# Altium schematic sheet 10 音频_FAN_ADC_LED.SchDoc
size 420 x 297 mm
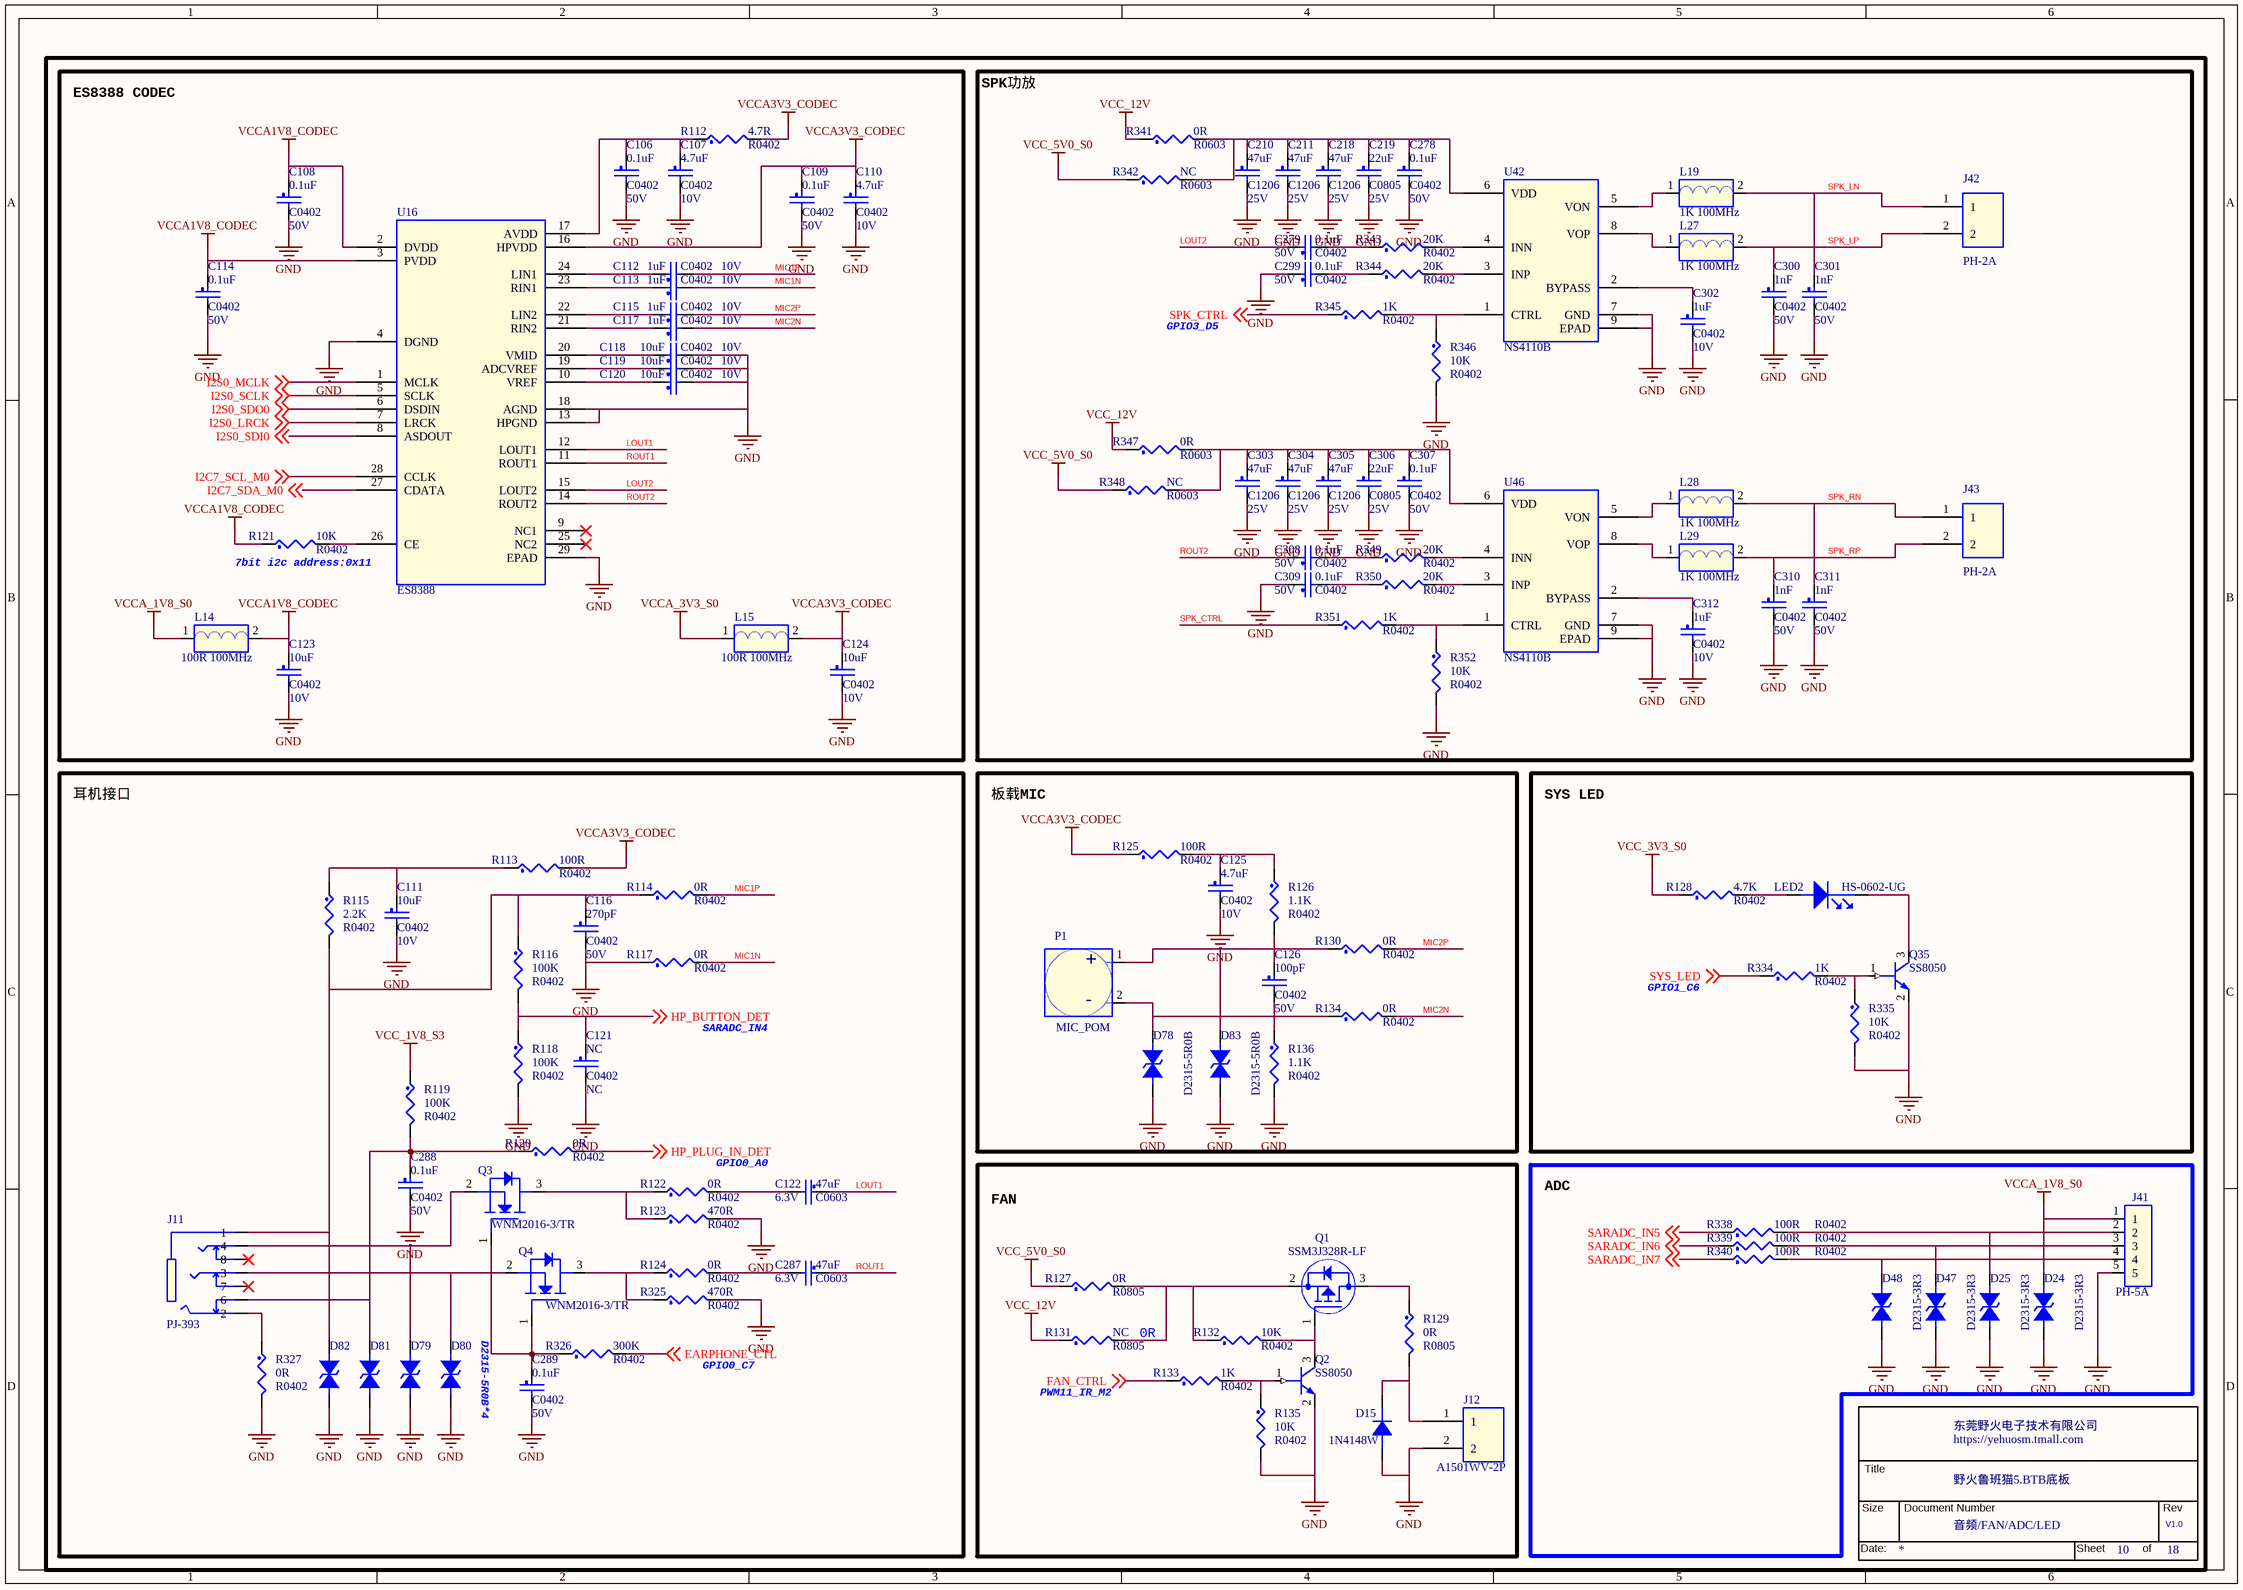
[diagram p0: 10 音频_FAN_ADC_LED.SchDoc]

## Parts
*  Doc: 音频/FAN/ADC/LED  RevCode: V1.0  Title: 野火鲁班猫5.BTB底板  OrgName: 东莞野火电子技术有限公司  Page Number: 10  Page Count: 18  (hidden comment: TitleBlock_YHSCH)  (graphical)
C106  0.1uF  Voltage: 50V  [C0402]
C107  4.7uF  Voltage: 10V  [C0402]
C108  0.1uF  Voltage: 50V  [C0402]
C109  0.1uF  Voltage: 50V  [C0402]
C110  4.7uF  Voltage: 10V  [C0402]
C111  10uF  Voltage: 10V  [C0402]
C112  1uF  Voltage: 10V  [C0402]
C113  1uF  Voltage: 10V  [C0402]
C114  0.1uF  Voltage: 50V  [C0402]
C115  1uF  Voltage: 10V  [C0402]
C116  270pF  Voltage: 50V  [C0402]
C117  1uF  Voltage: 10V  [C0402]
C118  10uF  Voltage: 10V  [C0402]
C119  10uF  Voltage: 10V  [C0402]
C120  10uF  Voltage: 10V  [C0402]
C121  NC  [C0402]
C122  47uF  Voltage: 6.3V  [C0603]
C123  10uF  Voltage: 10V  [C0402]
C124  10uF  Voltage: 10V  [C0402]
C125  4.7uF  Voltage: 10V  [C0402]
C126  100pF  Voltage: 50V  [C0402]
C210  47uF  Voltage: 25V  [C1206]
C211  47uF  Voltage: 25V  [C1206]
C218  47uF  Voltage: 25V  [C1206]
C219  22uF  Voltage: 25V  [C0805]
C278  0.1uF  Voltage: 50V  [C0402]
C279  0.1uF  Voltage: 50V  [C0402]
C287  47uF  Voltage: 6.3V  [C0603]
C288  0.1uF  Voltage: 50V  [C0402]
C289  0.1uF  Voltage: 50V  [C0402]
C299  0.1uF  Voltage: 50V  [C0402]
C300  1nF  Voltage: 50V  [C0402]
C301  1nF  Voltage: 50V  [C0402]
C302  1uF  Voltage: 10V  [C0402]
C303  47uF  Voltage: 25V  [C1206]
C304  47uF  Voltage: 25V  [C1206]
C305  47uF  Voltage: 25V  [C1206]
C306  22uF  Voltage: 25V  [C0805]
C307  0.1uF  Voltage: 50V  [C0402]
C308  0.1uF  Voltage: 50V  [C0402]
C309  0.1uF  Voltage: 50V  [C0402]
C310  1nF  Voltage: 50V  [C0402]
C311  1nF  Voltage: 50V  [C0402]
C312  1uF  Voltage: 10V  [C0402]
D15  1N4148W  [SOD-123]
D24  D2315-3R3  [D0603/SMD]
D25  D2315-3R3  [D0603/SMD]
D47  D2315-3R3  [D0603/SMD]
D48  D2315-3R3  [D0603/SMD]
D78  D2315-5R0B  [D0603/SMD]
D79  D2315-5R0B  [D0603/SMD]  (value not drawn)
D80  D2315-5R0B  [D0603/SMD]  (value not drawn)
D81  D2315-5R0B  [D0603/SMD]  (value not drawn)
D82  D2315-5R0B  [D0603/SMD]  (value not drawn)
D83  D2315-5R0B  [D0603/SMD]
J11  PJ-393  [audio_smd_7p_6r0x8r8]
J12  A1501WV-2P  [zh1p5mm_th_2p]
J41  PH-5A  [PH-1x5-2P0]
J42  PH-2A  [PH-1x2-2P0_l]
J43  PH-2A  [PH-1x2-2P0_l]
L14  100R 100MHz  [L0603]
L15  100R 100MHz  [L0603]
L19  1K 100MHz  [L0603]
L27  1K 100MHz  [L0603]
L28  1K 100MHz  [L0603]
L29  1K 100MHz  [L0603]
LED2  HS-0602-UG  [led_hs_0602_ur]
P1  MIC_POM  [MIC2-4R00-TM]
Q1  SSM3J328R-LF  [SOT23]
Q2  SS8050  [SOT23]
Q3  WNM2016-3/TR  [SOT23]
Q4  WNM2016-3/TR  [SOT23]
Q35  SS8050  [SOT23]
R112  4.7R  [R0402]
R113  100R  [R0402]
R114  0R  [R0402]
R115  2.2K  [R0402]
R116  100K  [R0402]
R117  0R  [R0402]
R118  100K  [R0402]
R119  100K  [R0402]
R120  0R  [R0402]
R121  10K  [R0402]
R122  0R  [R0402]
R123  470R  [R0402]
R124  0R  [R0402]
R125  100R  [R0402]
R126  1.1K  [R0402]
R127  0R  [R0805]
R128  4.7K  [R0402]
R129  0R  [R0805]
R130  0R  [R0402]
R131  NC  [R0805]
R132  10K  [R0402]
R133  1K  [R0402]
R134  0R  [R0402]
R135  10K  [R0402]
R136  1.1K  [R0402]
R325  470R  [R0402]
R326  300K  [R0402]
R327  0R  [R0402]
R334  1K  [R0402]
R335  10K  [R0402]
R338  100R  [R0402]
R339  100R  [R0402]
R340  100R  [R0402]
R341  0R  [R0603]
R342  NC  [R0603]
R343  20K  [R0402]
R344  20K  [R0402]
R345  1K  [R0402]
R346  10K  [R0402]
R347  0R  [R0603]
R348  NC  [R0603]
R349  20K  [R0402]
R350  20K  [R0402]
R351  1K  [R0402]
R352  10K  [R0402]
U16  ES8388  [qfn28_0r45-4x4EP2R6X2R6]
U42  NS4110B  [SOP-8-EP-2R5X3R4]
U46  NS4110B  [SOP-8-EP-2R5X3R4]

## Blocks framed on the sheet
ES8388 CODEC: C106-C110 C112-C115 C117-C120 C123 C124 L14 L15 R112 R121 U16
SPK功放: C210 C211 C218 C219 C278 C279 C299-C312 J42 J43 L19 L27-L29 R341-R352 U42 U46
耳机接口: C111 C116 C121 C122 C287-C289 D79-D82 J11 Q3 Q4 R113-R120 R122-R124 R325-R327
板载MIC: C125 C126 D78 D83 P1 R125 R126 R130 R134 R136
SYS LED: LED2 Q35 R128 R334 R335
FAN: D15 J12 Q1 Q2 R127 R129 R131-R133 R135
ADC: D24 D25 D47 D48 J41 R338-R340

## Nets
GND: C106.2 C107.2 C108.2 C109.2 C110.2 C111.2 C114.2 C116.2 C118.2 C119.2 C120.2 C121.2 C123.2 C124.2 C125.2 C210.2 C211.2 C218.2 C219.2 C278.2 C288.2 C289.2 C299.1 C300.2 C301.2 C302.2 C303.2 C304.2 C305.2 C306.2 C307.2 C309.1 C310.2 C311.2 C312.2 D15.2(A) D24.2 D25.2 D47.2 D48.2 D78.1 D79.1 D80.1 D81.1 D82.1 D83.1 J12.2 J41.5 Q2.2(EMITTER) Q35.2(EMITTER) R117.1 R118.2 R123.2 R135.2 R136.2 R325.2 R327.2 R335.2 R346.2 R352.2 U16.4(DGND) U16.13(HPGND) U16.18(AGND) U16.29(EPAD) U42.7(GND) U42.9(EPAD) U46.7(GND) U46.9(EPAD)
VCC_1V8_S3: R119.1
VCC_3V3_S0: R128.1
VCC_5V0_S0: R127.1 R342.1 R348.1
VCC_12V: R131.1 R341.1 R347.1
VCCA1V8_CODEC: C108.1 C114.1 C123.1 L14.2 R121.1 U16.2(DVDD) U16.3(PVDD)
VCCA3V3_CODEC: C109.1 C110.1 C124.1 L15.2 R112.2 R113.2 R125.1 U16.16(HPVDD)
VCCA_1V8_S0: D24.1 J41.1 L14.1
VCCA_3V3_S0: L15.1
EARPHONE_CTL: R326.2 ; off-sheet EARPHONE_CTL
FAN_CTRL: R133.1 ; off-sheet FAN_CTRL
HP_BUTTON_DET: C121.1 R116.2 R118.1 ; off-sheet HP_BUTTON_DET
HP_PLUG_IN_DET: R120.2 ; off-sheet HP_PLUG_IN_DET
I2C7_SCL_M0: U16.28(CCLK) ; off-sheet I2C7_SCL_M0
I2C7_SDA_M0: U16.27(CDATA) ; off-sheet I2C7_SDA_M0
I2S0_LRCK: U16.7(LRCK) ; off-sheet I2S0_LRCK
I2S0_MCLK: U16.1(MCLK) ; off-sheet I2S0_MCLK
I2S0_SCLK: U16.5(SCLK) ; off-sheet I2S0_SCLK
I2S0_SDI0: U16.8(ASDOUT) ; off-sheet I2S0_SDI0
I2S0_SDO0: U16.6(DSDIN) ; off-sheet I2S0_SDO0
LOUT1: C122.1 U16.12(LOUT1)
LOUT2: C279.1 U16.15(LOUT2)
MIC1N: C113.2 R117.2
MIC1P: C112.2 R114.2
MIC2N: C117.2 R134.2
MIC2P: C115.2 R130.2
ROUT1: C287.1 U16.11(ROUT1)
ROUT2: C308.1 U16.14(ROUT2)
SARADC_IN5: R338.1 ; off-sheet SARADC_IN5
SARADC_IN6: R339.1 ; off-sheet SARADC_IN6
SARADC_IN7: R340.1 ; off-sheet SARADC_IN7
SPK_CTRL: R345.1 R351.1 ; off-sheet SPK_CTRL
SPK_LN: C301.1 J42.1 L19.2
SPK_LP: C300.1 J42.2 L27.2
SPK_RN: C311.1 J43.1 L28.2
SPK_RP: C310.1 J43.2 L29.2
SYS_LED: R334.1 ; off-sheet SYS_LED
NetC106_1: C106.1 C107.1 R112.1 U16.17(AVDD)
NetC111_1: C111.1 R113.1 R115.1
NetC112_1: C112.1 U16.24(LIN1)
NetC113_1: C113.1 U16.23(RIN1)
NetC115_1: C115.1 U16.22(LIN2)
NetC116_1: C116.1 D82.2 J11.1 R114.1 R115.2 R116.1
NetC117_1: C117.1 U16.21(RIN2)
NetC118_1: C118.1 U16.20(VMID)
NetC119_1: C119.1 U16.19(ADCVREF)
NetC120_1: C120.1 U16.10(VREF)
NetC122_2: C122.2 R122.2
NetC125_1: C125.1 R125.2 R126.1
NetC126_1: C126.1 D83.2 P1.1(Out) R126.2 R130.1
NetC126_2: C126.2 D78.2 P1.2(GND) R134.1 R136.1
NetC210_1: C210.1 C211.1 C218.1 C219.1 C278.1 R341.2 R342.2 U42.6(VDD)
NetC279_2: C279.2 R343.1
NetC287_2: C287.2 R124.2
NetC288_1: C288.1 D81.2 J11.6 R119.2 R120.1
NetC289_1: C289.1 Q3.1(GATE) Q4.1(GATE) R326.1
NetC299_2: C299.2 R344.1
NetC302_1: C302.1 U42.2(BYPASS)
NetC303_1: C303.1 C304.1 C305.1 C306.1 C307.1 R347.2 R348.2 U46.6(VDD)
NetC308_2: C308.2 R349.1
NetC309_2: C309.2 R350.1
NetC312_1: C312.1 U46.2(BYPASS)
NetD15_1: D15.1(K) J12.1 R129.2
NetD25_1: D25.1 J41.2 R338.2
NetD47_1: D47.1 J41.3 R339.2
NetD48_1: D48.1 J41.4 R340.2
NetD79_2: D79.2 J11.4 Q3.2(SOURCE)
NetD80_2: D80.2 J11.3 Q4.2(SOURCE)
NetJ11_2: J11.2 R327.1
NetL19_1: L19.1 U42.5(VON)
NetL27_1: L27.1 U42.8(VOP)
NetL28_1: L28.1 U46.5(VON)
NetL29_1: L29.1 U46.8(VOP)
NetLED2_1: LED2.1(CATHODE) Q35.3(COLLECTOR)
NetLED2_2: LED2.2(ANODE) R128.2
NetQ1_1: Q1.1(GATE) Q2.3(COLLECTOR) R132.2
NetQ1_2: Q1.2(SOURCE) R127.2 R131.2 R132.1
NetQ1_3: Q1.3(DRAIN) R129.1
NetQ2_1: Q2.1(BASE) R133.2 R135.1
NetQ3_3: Q3.3(DRAIN) R122.1 R123.1
NetQ4_3: Q4.3(DRAIN) R124.1 R325.1
NetQ35_1: Q35.1(BASE) R334.2 R335.1
NetR121_2: R121.2 U16.26(CE)
NetR343_2: R343.2 U42.4(INN)
NetR344_2: R344.2 U42.3(INP)
NetR345_2: R345.2 R346.1 U42.1(CTRL)
NetR349_2: R349.2 U46.4(INN)
NetR350_2: R350.2 U46.3(INP)
NetR351_2: R351.2 R352.1 U46.1(CTRL)

Not connected (* = marked no-connect by the designer): J11 7* 8*; U16 9(NC1)* 25(NC2)*

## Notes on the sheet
- GPIO3_D5
- (near R121) 7bit i2c address:0x11
- GPIO1_C6
- SARADC_IN4
- (near R122) GPIO0_A0
- D2315-5R0B*4
- (near R131) 0R
- GPIO0_C7
- (near R131) PWM11_IR_M2

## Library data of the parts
* = TitleBlock_YHSCH: Cage Code: 1
C106 C108 C109 C114 C289 C299 C307 C308 = CAP_NP: CLASS: DISCRETE; 规格: 贴片电容0.1uF 10% 50V X5R 0402; 规格编号: 0402X104K500NT; 条码: EBF29060118; 品牌: 风华; 类别: 贴片电容0402; 规格书: 风华电容.pdf; 价格: 0.029826; 生命周期: 量产
C107 C110 = CAP_NP: CLASS: DISCRETE; 生命周期: 量产; 价格: 0.059058; 规格书: 国巨-贴片电容.pdf; 类别: 贴片电容0402; 品牌: 国巨; 条码: EBF29060248; 规格编号: CC0402KRX5R6BB475; 规格: 贴片电容4.7uF 10% 10V X5R 0402
C111 C118-C120 = CAP_NP: CLASS: DISCRETE; 规格: 贴片电容10uF 20% 10V X5R 0402; 规格编号: CL05A106MP8NUB8; 条码: EBF29060247; 品牌: 三星; 类别: 贴片电容0402; 规格书: 三星电容.pdf; 价格: 0.518415; 生命周期: 量产
C112 C113 C115 C117 C312 = CAP_NP: CLASS: DISCRETE; 生命周期: 量产; 价格: 0.01191; 规格书: 风华电容.pdf; 类别: 贴片电容0402; 品牌: 风华; 条码: EBF29060121; 规格编号: 0402X105K100NT; 规格: 贴片电容1uF 10% 10V X5R 0402
C116 = CAP_NP: CLASS: DISCRETE; 规格: 贴片电容270pF 5% 50V C0G 0402; 规格编号: 0402CG271J500NT; 条码: EBF29060290; 品牌: 风华; 类别: 贴片电容0402; 规格书: 风华电容.pdf; 价格: 0.018204; 生命周期: 量产
C121 = CAP_NP: CLASS: DISCRETE; 规格: 贴片电容NC 预留; 条码: EBF29060149; 类别: 贴片电容0402
C122 C287 = CAP_NP: CLASS: DISCRETE; 规格: 贴片电容47uF 20% 6.3V X5R 0603; 规格编号: CL10A476MQ8QRNC; 条码: EBF29060263; 品牌: 三星; 类别: 贴片电容0603; 规格书: 三星电容.pdf; 价格: 0.420524; 生命周期: 量产
C123 C124 = CAP_NP: CLASS: DISCRETE; 生命周期: 量产; 价格: 0.518415; 规格书: 三星电容.pdf; 类别: 贴片电容0402; 品牌: 三星; 条码: EBF29060247; 规格编号: CL05A106MP8NUB8; 规格: 贴片电容10uF 20% 10V X5R 0402
C125 = CAP_NP: CLASS: DISCRETE; 规格: 贴片电容4.7uF 10% 10V X5R 0402; 规格编号: CC0402KRX5R6BB475; 条码: EBF29060248; 品牌: 国巨; 类别: 贴片电容0402; 规格书: 国巨-贴片电容.pdf; 价格: 0.059058; 生命周期: 量产
C126 = CAP_NP: CLASS: DISCRETE; 生命周期: 量产; 价格: 0.034837; 规格书: 村田040系列贴片电容.pdf; 类别: 贴片电容0402; 品牌: 村田; 条码: EBF29060302; 规格编号: GRT1555C1H101JA; 规格: 贴片电容100pF 5% 50V C0G 0402
C210 C211 C218 = CAP_NP: CLASS: DISCRETE; 规格: 贴片电容47uF 20% 25V X5R 1206; 规格编号: GRM31CR61E476ME44L; 条码: EBF29060192; 品牌: 村田; 类别: 贴片电容1206; 规格书: 村田贴片电容.pdf; 价格: 1.12; 生命周期: 量产
C219 C306 = CAP_NP: CLASS: DISCRETE; 规格: 贴片电容22uF 20% 25V X5R 0805; 规格编号: 0805X226M250NT; 条码: EBF29060173; 品牌: 风华; 类别: 贴片电容0805; 规格书: 风华电容.pdf; 价格: 0.285631; 生命周期: 量产
C278 C279 C288 C309 = CAP_NP: CLASS: DISCRETE; 生命周期: 量产; 价格: 0.029826; 规格书: 风华电容.pdf; 类别: 贴片电容0402; 品牌: 风华; 条码: EBF29060118; 规格编号: 0402X104K500NT; 规格: 贴片电容0.1uF 10% 50V X5R 0402
C300 C301 = CAP_NP: CLASS: DISCRETE; 规格: 贴片电容1nF 20% 50V X7R 0402; 规格编号: 0402B102M500NT; 条码: EBF29060175; 品牌: 风华; 类别: 贴片电容0402; 规格书: 风华电容.pdf; 价格: 0.006195; 生命周期: 量产
C302 = CAP_NP: CLASS: DISCRETE; 规格: 贴片电容1uF 10% 10V X5R 0402; 规格编号: 0402X105K100NT; 条码: EBF29060121; 品牌: 风华; 类别: 贴片电容0402; 规格书: 风华电容.pdf; 价格: 0.01191; 生命周期: 量产
C303-C305 = CAP_NP: CLASS: DISCRETE; 生命周期: 量产; 价格: 1.12; 规格书: 村田贴片电容.pdf; 类别: 贴片电容1206; 品牌: 村田; 条码: EBF29060192; 规格编号: GRM31CR61E476ME44L; 规格: 贴片电容47uF 20% 25V X5R 1206
C310 C311 = CAP_NP: CLASS: DISCRETE; 生命周期: 量产; 价格: 0.006195; 规格书: 风华电容.pdf; 类别: 贴片电容0402; 品牌: 风华; 条码: EBF29060175; 规格编号: 0402B102M500NT; 规格: 贴片电容1nF 20% 50V X7R 0402
D15 = DIODE: 丝印: T4; 生命周期: 量产; 价格: 0.061637; 规格书: 1N4148WT4.pdf; 类别: 贴片开关二极管; 品牌: 江苏长电; 条码: EBF29140015; 规格: 开关二极管 反向耐压值100V 平均整流电流150mA 正向压降1.25V 150mA 功率500mW
D24 D25 D47 D48 = DIODE BI-DIR TRIG: PCB Footprint: esd0402; 生命周期: 量产; 规格书: 千虹_D2315-3R3.pdf; 类别: 贴片ESD; 品牌: 千虹; 条码: EBFCIS240517170749; 规格: 防静电保护ESD二极管 反向工作电压3.3V 击穿电压3.5V 钳位电压9V 结电容Cj 10pF; 备注: 通用
D78 D80 D83 = DIODE BI-DIR TRIG: PCB Footprint: esd0402; 规格: 防静电保护ESD二极管 反向工作电压5V 击穿电压7V 钳位电压10.5V 结电容Cj 0.3pF; 条码: EBFCIS240517170922; 品牌: 千虹; 类别: 贴片ESD; 规格书: 千虹_D2315-5R0B.pdf; 生命周期: 量产; 备注: 通用
D79 D81 D82 = DIODE BI-DIR TRIG: PCB Footprint: esd0402; 备注: 通用; 生命周期: 量产; 规格书: 千虹_D2315-5R0B.pdf; 类别: 贴片ESD; 品牌: 千虹; 条码: EBFCIS240517170922; 规格: 防静电保护ESD二极管 反向工作电压5V 击穿电压7V 钳位电压10.5V 结电容Cj 0.3pF
J11 = PJ-393: 规格: PJ-393_3.5MM四段式耳机插座_7pin; 条码: EBF29040116; 类别: 耳机座; 规格书: PJ-393_3.5MM四段式耳机插座_7pin.pdf; 生命周期: 量产; 品牌: 品赞
J12 = 1X2PIN: 生命周期: 量产; 规格书: 长江连接器_A1501WV-2P.PDF; 类别: 线对板连接器; 品牌: 长江连接器; 条码: EBF29040095; 规格: ZH1.5直插 镀锡 2P 针座连接器
J41 = 1X5PIN: 规格: 直针PH2.0-5P 间距2.0MM 拔插式 接插件; 条码: EBF29040028; 品牌: 博穆精密; 类别: PH连接器; 规格书: 博穆精密-PH2.0.pdf; 价格: 0.046679; 生命周期: 量产
J42 J43 = 1X2PIN: 可替代料: EBF29040005; 生命周期: 量产; 价格: 0.019031; 规格书: 博穆精密_PH2.0-A.pdf; 类别: PH连接器; 品牌: 博穆精密; 规格: 直针PH2.0-2P 间距2.0MM 拔插式 接插件
L14 = BEAD: CLASS: DISCRETE; 生命周期: 量产; 价格: 0.021567; 规格书: 顺络-磁珠.pdf; 类别: 贴片磁珠0603; 品牌: 顺络; 条码: EBF29050038; 规格编号: UPZ1608E101-3R0TF; 规格: 磁珠100Ω @100MHz 额定电流3A 直流电阻30mΩ
L15 = BEAD: CLASS: DISCRETE; 规格: 磁珠100Ω @100MHz 额定电流3A 直流电阻30mΩ; 规格编号: UPZ1608E101-3R0TF; 条码: EBF29050038; 品牌: 顺络; 类别: 贴片磁珠0603; 规格书: 顺络-磁珠.pdf; 价格: 0.021567; 生命周期: 量产
L19 L27 = BEAD: CLASS: DISCRETE; 规格: 磁珠1K@100MHz额定电流600mA直流电阻350mΩ; 规格编号: BLM18HE102SN1D; 条码: EBFCIS230428095012; 品牌: 村田; 类别: 贴片磁珠0603; 规格书: 村田_BLM18H_SN系列磁珠.pdf; 价格: 0.149038; 生命周期: 量产; 备注: RK3566广告机
L28 L29 = BEAD: CLASS: DISCRETE; 生命周期: 量产; 价格: 0.149038; 规格书: 村田_BLM18H_SN系列磁珠.pdf; 类别: 贴片磁珠0603; 品牌: 村田; 条码: EBFCIS230428095012; 规格编号: BLM18HE102SN1D; 规格: 磁珠1K@100MHz额定电流600mA直流电阻350mΩ; 备注: RK3566广告机
LED2 = LED: 生命周期: 量产; 价格: 0.068705; 规格书: HS-0602-UG.pdf; 类别: 侧贴发光LED; 品牌: 鸿之森; 条码: EBF29140060; 规格: 正向电压(VF)：3.2V 工作电流：5mA 功率：80mW 绿色
P1 = MIC_POM: CLASS: IC; 规格: 4*1.2mm咪头 双电容驻极体话筒 拾音器 工作电压1.5V-10V 灵敏度-62DB 低阻抗; 规格编号: GMI4015P-2C-62db; 条码: EBFCIS221130183008; 品牌: 赢海; 类别: 麦克风; 规格书: 赢海_GMI4015P-2C-62db.pdf; 价格: 0.868384; 生命周期: 量产
Q1 = MOSFET_P: CLASS: IC; 规格: P沟道MOS 导通电阻29.8mΩ 电流3A 1.5V可驱动; 规格编号: SSM3J328R LF; 条码: EBF29280008; 品牌: 东芝; 类别: P-MOS; 规格书: SSM3J328R-LF.pdf; 价格: 0.447836; 生命周期: 量产; 丝印: KFH-XXX
Q2 Q35 = NPN: CLASS: IC; 规格: 贴片三极管SS8050 集电极电流1.5A 额定功率300mW NPN; 条码: EBF29090001; 品牌: 江苏长电; 类别: 贴片三极管SOT-23; 规格书: 江苏长电-SS8050Y1.pdf; 价格: 0.086744; 生命周期: 量产; 丝印: Y1
Q3 = MOSFET N: 规格: N沟道MOS 导通电阻47mΩ 电流3.6A 4.5V 阈值电压(Vgs(th)@Id)1V 连续漏极电流2.9A; 条码: EBF29280014; 品牌: 韦尔; 类别: N-MOS; 规格书: WNM2016-3_TR.pdf; 备注: 立创停售
Q4 = MOSFET N: 备注: 立创停售; 规格书: WNM2016-3_TR.pdf; 类别: N-MOS; 品牌: 韦尔; 条码: EBF29280014; 规格: N沟道MOS 导通电阻47mΩ 电流3.6A 4.5V 阈值电压(Vgs(th)@Id)1V 连续漏极电流2.9A
R112 = RES: CLASS: DISCRETE; 规格: 贴片电阻4.7R 1% 1/16W 0402; 规格编号: 0402WGF470KTCE; 条码: EBFCIS221112135607; 品牌: 厚声; 类别: 贴片电阻0402; 规格书: 厚声-无铅厚膜电阻.pdf; 价格: 0.003317; 生命周期: 量产
R113 = RES: CLASS: DISCRETE; 规格: 贴片电阻100R 1% 1/16W 0402; 规格编号: RI0402L1000FT; 条码: EBF29070053; 品牌: 合科泰; 类别: 贴片电阻0402; 规格书: 合科泰-RI系列电阻.pdf; 生命周期: 量产
R114 R117 R120 R122 R124 R130 R327 = RES: CLASS: DISCRETE; 生命周期: 量产; 规格书: 合科泰-RI系列电阻.pdf; 类别: 贴片电阻0402; 品牌: 合科泰; 条码: EBF29070049; 规格编号: RI0402L000FT; 规格: 贴片电阻0R 1% 1/16W 0402
R115 = RES: CLASS: DISCRETE; 规格: 贴片电阻2.2K 1% 1/16W 0402; 规格编号: RI0402L2201FT; 条码: EBF29070051; 品牌: 合科泰; 类别: 贴片电阻0402; 规格书: 合科泰-RI系列电阻.pdf; 生命周期: 量产
R116 R118 = RES: CLASS: DISCRETE; 生命周期: 量产; 规格书: 合科泰-RI系列电阻.pdf; 类别: 贴片电阻0402; 品牌: 合科泰; 条码: EBF29070054; 规格编号: RI0402L1003FT; 规格: 贴片电阻100K 1% 1/16W 0402
R119 = RES: CLASS: DISCRETE; 规格: 贴片电阻100K 1% 1/16W 0402; 规格编号: RI0402L1003FT; 条码: EBF29070054; 品牌: 合科泰; 类别: 贴片电阻0402; 规格书: 合科泰-RI系列电阻.pdf; 生命周期: 量产
R121 R346 = RES: CLASS: DISCRETE; 生命周期: 量产; 价格: 0.002773; 规格书: 厚声-无铅厚膜电阻.pdf; 类别: 贴片电阻0402; 品牌: 厚声; 条码: EBF29070046; 规格编号: 0402WGF1002TCE; 规格: 贴片电阻10K 1% 1/16W 0402
R123 R325 = RES: CLASS: DISCRETE; 规格: 贴片电阻470R 1% 1/16W 0402; 规格编号: 0402WGF4700TCE; 条码: EBF29070284; 品牌: 厚声; 类别: 贴片电阻0402; 规格书: 厚声-无铅厚膜电阻.pdf; 价格: 0.002728; 生命周期: 量产
R125 R338-R340 = RES: CLASS: DISCRETE; 生命周期: 量产; 规格书: 合科泰-RI系列电阻.pdf; 类别: 贴片电阻0402; 品牌: 合科泰; 条码: EBF29070053; 规格编号: RI0402L1000FT; 规格: 贴片电阻100R 1% 1/16W 0402
R126 R136 = RES: CLASS: DISCRETE; 规格: 贴片电阻1.1K 1% 1/16W 0402; 规格编号: 0402WGF1101TCE; 条码: EBFCIS221112135212; 品牌: 厚声; 类别: 贴片电阻0402; 规格书: 厚声-无铅厚膜电阻.pdf; 价格: 0.001622; 生命周期: 量产
R127 = RES: CLASS: DISCRETE; 生命周期: 量产; 规格书: 合科泰-RI系列电阻.pdf; 类别: 贴片电阻0805; 品牌: 合科泰; 条码: EBF29070064; 规格编号: RI0805L0000FT; 规格: 贴片电阻0R 1% 1/8W 0805
R128 = RES: CLASS: DISCRETE; 生命周期: 量产; 规格书: 合科泰-RI系列电阻.pdf; 类别: 贴片电阻0402; 品牌: 合科泰; 条码: EBF29070047; 规格编号: RI0402L4701FT; 规格: 贴片电阻4.7K 1% 1/16W 0402
R129 = RES: CLASS: DISCRETE; 规格: 贴片电阻0R 1% 1/8W 0805; 规格编号: RI0805L0000FT; 条码: EBF29070064; 品牌: 合科泰; 类别: 贴片电阻0805; 规格书: 合科泰-RI系列电阻.pdf; 生命周期: 量产
R131 = RES: CLASS: DISCRETE; 类别: 贴片电阻0805; 条码: EBF29070089; 规格: 贴片电阻NC 预留
R132 R135 R335 R352 = RES: CLASS: DISCRETE; 规格: 贴片电阻10K 1% 1/16W 0402; 规格编号: 0402WGF1002TCE; 条码: EBF29070046; 品牌: 厚声; 类别: 贴片电阻0402; 规格书: 厚声-无铅厚膜电阻.pdf; 价格: 0.002773; 生命周期: 量产
R133 R334 R345 = RES: CLASS: DISCRETE; 生命周期: 量产; 规格书: 合科泰-RI系列电阻.pdf; 类别: 贴片电阻0402; 品牌: 合科泰; 条码: EBF29070050; 规格编号: RI0402L1001FT; 规格: 贴片电阻1K 1% 1/16W 0402
R134 = RES: CLASS: DISCRETE; 规格: 贴片电阻0R 1% 1/16W 0402; 规格编号: RI0402L000FT; 条码: EBF29070049; 品牌: 合科泰; 类别: 贴片电阻0402; 规格书: 合科泰-RI系列电阻.pdf; 生命周期: 量产
R326 = RES: CLASS: DISCRETE; 规格: 贴片电阻300K 1% 1/16W 0402; 规格编号: RI0402L3003FT; 条码: EBF29070220; 品牌: 合科泰; 类别: 贴片电阻0402; 规格书: 合科泰-RI系列电阻.pdf; 生命周期: 量产
R341 R347 = RES: CLASS: DISCRETE; 生命周期: 量产; 规格书: 合科泰-RI系列电阻.pdf; 类别: 贴片电阻0603; 品牌: 合科泰; 条码: EBF29070063; 规格编号: RI0603L0000FT; 规格: 贴片电阻0R 1% 1/10W 0603
R342 R348 = RES: CLASS: DISCRETE; 类别: 贴片电阻0603; 条码: EBF29070088; 规格: 贴片电阻NC 预留
R343 R344 = RES: CLASS: DISCRETE; 规格: 贴片电阻20K 1% 1/16W 0402; 规格编号: 0402WGF2002TCE; 条码: EBF29070223; 品牌: 厚声; 类别: 贴片电阻0402; 规格书: 厚声-无铅厚膜电阻.pdf; 价格: 0.002473; 生命周期: 量产
R349 R350 = RES: CLASS: DISCRETE; 生命周期: 量产; 价格: 0.002473; 规格书: 厚声-无铅厚膜电阻.pdf; 类别: 贴片电阻0402; 品牌: 厚声; 条码: EBF29070223; 规格编号: 0402WGF2002TCE; 规格: 贴片电阻20K 1% 1/16W 0402
R351 = RES: CLASS: DISCRETE; 规格: 贴片电阻1K 1% 1/16W 0402; 规格编号: RI0402L1001FT; 条码: EBF29070050; 品牌: 合科泰; 类别: 贴片电阻0402; 规格书: 合科泰-RI系列电阻.pdf; 生命周期: 量产
U16 = ES8388: 价格: 3.904; 规格书: 顺芯_ES8388.pdf; 类别: 音频芯片; 品牌: 顺芯; 条码: EBFCIS221116105415; 规格: 音频接口芯片 模拟供电1.7V~3.6V 核心与IO供电1.5V~3.6V
U42 U46 = NS4110B: 规格: 单声道AB/D类音频功率放大器 工作电压:6V~14V 输出功率:18W@4Ω 超低EMI 支持差分输入; 条码: EBFCIS230518164803; 品牌: 纳芯威; 类别: 音频芯片; 规格书: 纳芯威_NS4110B音频功放.pdf; 生命周期: 量产; 备注: RK3566广告机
